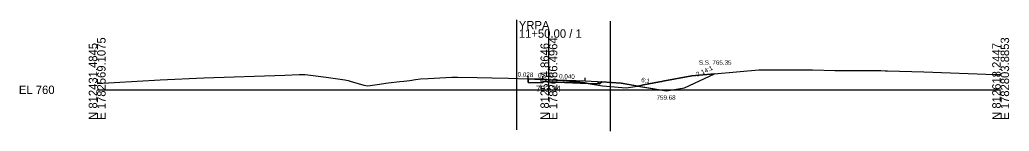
# Model space of a CAD drawing. Extents: x -26 to 2603, y -14 to 9545.
# Drawn here: x -25.7 to 302.8, y 1486.2 to 1523.4 of the extents above; entities that cross this region are included whole.
import ezdxf

# ---------------------------------------------------------------- set-up
doc = ezdxf.new("R2010")
doc.units = 0
for name, color, linetype in [('Exist Cross Section Cell', 7, 'Continuous'), ('Exist XS Center Line Elevation Label', 7, 'Continuous'), ('Exist XS Ground Line', 7, 'Continuous'), ('Prop XS Ditch Slope Text', 7, 'Continuous'), ('Prop XS Ditch Standard Text', 7, 'Continuous'), ('Prop XS Dump Level', 7, 'Continuous'), ('Prop XS Earthwork Shape', 7, 'Continuous'), ('Prop XS EOT Tick Mark', 7, 'Continuous'), ('Prop XS Exc Vertical Line 1', 7, 'Continuous'), ('Prop XS Exc Vertical Line 2', 7, 'Continuous'), ('Prop XS Finish Grade', 7, 'Continuous'), ('Prop XS Finish Grade Earthwork', 7, 'Continuous'), ('Prop XS Finish Grade Paved Shoulder', 7, 'Continuous'), ('Prop XS Finish Grade Pavement', 7, 'Continuous'), ('Prop XS Pvmt Edge Slope', 7, 'Continuous'), ('Prop XS SE Text', 7, 'Continuous'), ('Prop XS Side Slope Text', 7, 'Continuous'), ('Prop XS SS Elevation Text', 7, 'Continuous'), ('Prop XS Subgrade Earthwork', 7, 'Continuous'), ('Scratch_Level_6', 7, 'Continuous')]:
    doc.layers.add(name, color=color, linetype=linetype)

msp = doc.modelspace()

# ---------------------------------------------------------------- linework, layer by layer
at = {"layer": 'Exist Cross Section Cell'}
for p, q in [((150, 1500), (150, 1520.14)), ((0, 1500), (150, 1500)), ((150, 1500), (300, 1500))]:
    msp.add_line(p, q, dxfattribs=at)
at = {"layer": 'Exist XS Ground Line'}
for p, q in [((35.42, 1504.02), (62.35, 1504.9)), ((62.35, 1504.9), (67.02, 1505.05)), ((67.02, 1505.05), (69.05, 1505.1)), ((69.05, 1505.1), (69.99, 1505)), ((69.99, 1505), (76.06, 1504.17)), ((197.45, 1504.65), (219.71, 1506.71)), ((219.71, 1506.71), (237.52, 1506.62)), ((237.52, 1506.62), (244.92, 1506.46)), ((244.92, 1506.46), (260.17, 1506.45)), ((260.17, 1506.45), (261.68, 1506.34)), ((261.68, 1506.34), (262.39, 1506.32)), ((262.39, 1506.32), (274.49, 1506.04)), ((274.49, 1506.04), (298.04, 1505.13)), ((298.04, 1505.13), (300, 1505.14)), ((0, 1502.11), (5.69, 1502.46)), ((5.69, 1502.46), (20.89, 1503.37)), ((20.89, 1503.37), (35.42, 1504.02)), ((76.06, 1504.17), (82.2, 1503.34)), ((82.2, 1503.34), (83.37, 1503.07)), ((83.37, 1503.07), (84.02, 1502.87)), ((84.02, 1502.87), (88.59, 1501.6)), ((88.59, 1501.6), (89.91, 1501.37)), ((89.91, 1501.37), (92.99, 1501.8)), ((92.99, 1501.8), (96.62, 1502.27)), ((96.62, 1502.27), (100.47, 1502.74)), ((100.47, 1502.74), (101.83, 1502.92)), ((101.83, 1502.92), (103.78, 1503.15)), ((103.78, 1503.15), (105.67, 1503.43)), ((105.67, 1503.43), (107.38, 1503.66)), ((107.38, 1503.66), (109.95, 1503.8)), ((109.95, 1503.8), (115.76, 1504.07)), ((115.76, 1504.07), (117.74, 1504.16)), ((117.74, 1504.16), (119.62, 1504.25)), ((119.62, 1504.25), (126.19, 1504.11)), ((126.19, 1504.11), (131.04, 1504.01)), ((131.04, 1504.01), (136.6, 1503.85)), ((136.6, 1503.85), (143.11, 1503.67)), ((143.11, 1503.67), (145.35, 1503.54)), ((145.35, 1503.54), (147.35, 1503.42)), ((147.35, 1503.42), (149.31, 1503.38)), ((149.31, 1503.38), (150, 1503.34)), ((150, 1503.34), (154.6, 1503.07)), ((154.6, 1503.07), (161.35, 1502.41)), ((161.35, 1502.41), (167.83, 1501.36)), ((180.03, 1501.36), (181.38, 1501.64)), ((181.38, 1501.64), (186.72, 1502.62)), ((186.72, 1502.62), (187.45, 1502.76)), ((187.45, 1502.76), (187.8, 1502.84)), ((187.8, 1502.84), (197.45, 1504.65)), ((167.83, 1501.36), (169.1, 1501.2)), ((169.1, 1501.2), (175.7, 1500.71)), ((175.7, 1500.71), (178.62, 1501.12)), ((178.62, 1501.12), (180.03, 1501.36))]:
    msp.add_line(p, q, dxfattribs=at)
at = {"layer": 'Prop XS Dump Level'}
for p, q in [((148, 1503.54), (150, 1503.46)), ((150, 1503.46), (162, 1502.98))]:
    msp.add_line(p, q, dxfattribs=at)
at = {"layer": 'Prop XS Earthwork Shape'}
for points in [[(195, 1500.68), (205, 1505.35), (197.45, 1504.65), (187.8, 1502.84), (187.45, 1502.76), (186.72, 1502.62), (181.38, 1501.64), (180.03, 1501.36), (179.48, 1501.26), (189, 1499.68)], [(161.35, 1502.41), (163.01, 1502.14), (149.97, 1502.66), (148, 1502.74), (148, 1502.29), (143.1, 1502.42), (143.1, 1503.67), (145.35, 1503.54), (147.35, 1503.42), (149.31, 1503.38), (150, 1503.34), (154.6, 1503.07)], [(163.01, 1502.14), (167.83, 1501.36), (169.1, 1501.2), (175.7, 1500.71), (178.62, 1501.12), (179.48, 1501.26), (174, 1502.18), (167.53, 1502.69), (166.83, 1501.99)]]:
    msp.add_lwpolyline(points, close=True, dxfattribs=at)
at = {"layer": 'Prop XS EOT Tick Mark'}
for p, q in [((143.1, 1503.67), (143.1, 1504.62)), ((148, 1503.54), (148, 1504.54)), ((162, 1502.98), (162, 1503.98))]:
    msp.add_line(p, q, dxfattribs=at)
at = {"layer": 'Prop XS Exc Vertical Line 1'}
msp.add_line((139.38, 1486.66), (139.38, 1523.35), dxfattribs=at)
at = {"layer": 'Prop XS Exc Vertical Line 2'}
msp.add_line((170.44, 1486.18), (170.44, 1522.87), dxfattribs=at)
at = {"layer": 'Prop XS Finish Grade'}
msp.add_line((166, 1502.82), (167.53, 1502.69), dxfattribs=at)
at = {"layer": 'Prop XS Finish Grade Earthwork'}
for p, q in [((195, 1500.68), (205, 1505.35)), ((167.53, 1502.69), (174, 1502.18)), ((174, 1502.18), (189, 1499.68)), ((189, 1499.68), (195, 1500.68))]:
    msp.add_line(p, q, dxfattribs=at)
at = {"layer": 'Prop XS Finish Grade Paved Shoulder'}
for p, q in [((148, 1503.54), (143.1, 1503.67)), ((162, 1502.98), (166, 1502.82))]:
    msp.add_line(p, q, dxfattribs=at)
at = {"layer": 'Prop XS Finish Grade Pavement'}
for p, q in [((148, 1503.54), (150, 1503.46)), ((150, 1503.46), (162, 1502.98))]:
    msp.add_line(p, q, dxfattribs=at)
at = {"layer": 'Prop XS Pvmt Edge Slope'}
msp.add_line((166, 1502.82), (166.83, 1501.99), dxfattribs=at)
at = {"layer": 'Prop XS Subgrade Earthwork'}
for p, q in [((143.1, 1502.42), (143.1, 1503.67)), ((148, 1502.29), (143.1, 1502.42)), ((148, 1502.74), (149.97, 1502.66)), ((148, 1502.29), (148, 1502.74)), ((149.97, 1502.66), (166.83, 1501.99)), ((166.83, 1501.99), (167.53, 1502.69))]:
    msp.add_line(p, q, dxfattribs=at)
at = {"layer": 'Scratch_Level_6'}
msp.add_lwpolyline([(148, 1502.74), (149.97, 1502.66), (163.01, 1502.14), (161.35, 1502.41), (154.6, 1503.07), (150, 1503.34), (149.31, 1503.38), (147.35, 1503.42), (145.35, 1503.54), (143.1, 1503.67), (143.1, 1502.42), (148, 1502.29)], close=True, dxfattribs=at)

# ---------------------------------------------------------------- texts
at = {"layer": 'Exist Cross Section Cell'}
for s, p in [('YRPA', (140, 1520.14)), ('11+50.00 / 1', (140, 1517.34)), ('EL 760', (-26, 1498.6))]:
    msp.add_text(s, height=2.8, dxfattribs=at).set_placement(p)
for s, p in [('N 812431.4845', (0, 1490)), ('E 1782569.1075', (2.8, 1490)), ('N 812524.8646', (150, 1490)), ('E 1782686.4964', (152.8, 1490)), ('N 812618.2447', (300, 1490)), ('E 1782803.8853', (302.8, 1490))]:
    msp.add_text(s, height=2.8, rotation=90, dxfattribs=at).set_placement(p)
at = {"layer": 'Exist XS Center Line Elevation Label'}
msp.add_text('763.34', height=2, dxfattribs=at).set_placement((145.72, 1499.34))
at = {"layer": 'Prop XS Ditch Slope Text'}
msp.add_text('6:1', height=1.5, rotation=350.5377, dxfattribs=at).set_placement((180.55, 1502.6))
at = {"layer": 'Prop XS Ditch Standard Text'}
msp.add_text('759.68', height=1.5, dxfattribs=at).set_placement((185.74, 1496.68))
at = {"layer": 'Prop XS Dump Level'}
msp.add_text('Case4', height=0.04, dxfattribs=at).set_placement((174, 1502.14))
at = {"layer": 'Prop XS SE Text'}
for s, p in [('0.028', (139.59, 1504.42)), ('0.040', (146.38, 1504.1)), ('0.040', (153.38, 1503.82))]:
    msp.add_text(s, height=1.5, rotation=357.7094, dxfattribs=at).set_placement(p)
at = {"layer": 'Prop XS Side Slope Text'}
msp.add_text('2.14:1', height=1.5, rotation=25.0642, dxfattribs=at).set_placement((199.36, 1504.37))
at = {"layer": 'Prop XS SS Elevation Text'}
msp.add_text('S.S. 765.35', height=1.5, dxfattribs=at).set_placement((199.8, 1508.35))

doc.saveas('drawing.dxf')
